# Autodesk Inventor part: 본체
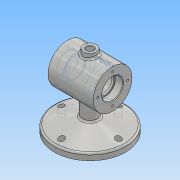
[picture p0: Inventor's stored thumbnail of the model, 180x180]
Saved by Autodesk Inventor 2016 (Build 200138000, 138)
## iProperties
Created: 2018-12
Part Number: 본체
Material: 알루미늄 6061
Document SubType Name: Modeling
Designer: Administrator
Density: 2.7 g/cm^3
Appearance: 알루미늄 - 평지
Mass: 664.863 g
Surface Area: 549.946 cm^2
Volume: 246.246 cm^3
Author: Administrator
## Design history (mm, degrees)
sketch "스케치2"
  geometry: L1 (0, 0)-(70, 0); L2 (70, 0)-(70, 30); L3 (70, 30)-(0, 30); L4 (0, 30)-(0, 0); L5 (0, 16)-(12, 16); L6 (12, 16)-(12, 14); L7 (12, 14)-(15, 14); L8 (15, 14)-(15, 25); L9 (15, 25)-(55, 25); L10 (55, 25)-(55, 14); L11 (55, 14)-(58, 14); L12 (58, 14)-(58, 16); L13 (58, 16)-(70, 16)
  constraints: 26 end point, 7 perpendicular, 6 point on line, 2 horizontal, 2 parallel
  dimensions: "d0" = 70 distance between parallel lines of L2 L4; "d1" = 32 diameter of L5 L1; "d2" = 28 diameter of L7 L1; "d3" = 3 distance between parallel lines of L6 L8; "d4" = 50 diameter of L9 L1; "d5" = 3 distance between parallel lines of L12 L10; "d6" = 60 diameter of L3 L1; "d13" = 40 distance between parallel lines of L10 L8; "d14" = 12 distance between parallel lines of L4 L6
revolve "회전1" sketch "스케치2" stored, may be unused: angle "d7" = 90 deg
fillet "모깎기1" dims "d8" = 3
fillet "모깎기2" dims "d9" = 0.3
chamfer "모따기1" distance "d10" = 1; stored, may be unused: second distance "d11" = 2, angle "d12" = 45 deg
node "작업 평면1"
sketch "스케치3"
  geometry: L1 (0, -30)-(0, 30) reference; L2 (0, 30)-(70, 30) reference; L3 (0, -30)-(70, -30) reference; L4 (35, 30)-(35, -30); C1 r 10 at (35, 0); 2 further points
  constraints: 3 midpoint, 2 end point, 1 centre point, 1 coincident
  dimensions: "d16" = 20 diameter of C1; "d19" = 35 distance between parallel lines of L1 L4 (derived)
extrude "돌출1" join sketch "스케치3" stored distance "d20" = 7; taper "d21" = 0 deg
hole "구멍1" diameter "d24" = 10; stored, may be unused: countersink angle "d28" = 90 deg, drill point angle "d30" = 0 deg; dims "d22" = 10, "d23" = 10, "d25" = 6, "d26" = 4, "d27" = 2, "d29" = 8
chamfer "모따기2" distance "d31" = 1; stored, may be unused: second distance "d32" = 2, angle "d33" = 45 deg
sketch "스케치4" dims "d34" = 46
  geometry: L1 (0, 0)-(-30, 0); 3 further points
  constraints: 2 end point, 2 horizontal alignment, 1 coincident, 1 horizontal, 1 point on line, 3 other
hole "구멍2" sketch "스케치4" at (-23, 0) diameter "d35" = 3.242; stored, may be unused: countersink angle "d39" = 90 deg, drill point angle "d41" = 118 deg; dims "d36" = 8, "d37" = 12.24, "d38" = 3.58, "d40" = 10
node "작업 평면2"
fillet "모깎기3" dims "d46" = 3
node "작업 평면3"
sketch "스케치5"
  geometry: L1 (52, 25)-(52, -25) reference; L2 (18, -25)-(18, 25) reference; C1 r 55 at (35, 0); 3 further points
  constraints: 1 centre point, 1 vertical alignment, 2 other
  dimensions: "d48" = 110 diameter of C1
extrude "돌출2" join sketch "스케치5" distance "d49" = 10; taper "d50" = 0 deg
sketch "스케치6" dims "d51" = 88
  geometry: L1 (0, 0)-(0, -44); C1 r 55 at (0, 0) reference; C2 r 44 at (0, 0); 1 further point
  constraints: 2 coincident, 2 end point, 1 centre point, 1 vertical, 1 vertical alignment, 3 other
extrude "돌출3" join sketch "스케치6" distance "d52" = 11; taper "d53" = -75 deg
sketch "스케치8"
  geometry: C1 r 13.947 at (0, 0) reference; C2 r 12 at (0, 0); 1 further point
  constraints: 1 centre point, 1 coincident
  dimensions: "d58" = 24 diameter of C2
extrude "돌출4" join sketch "스케치8" stored distance "d59" = 1; taper "d60" = 0 deg
fillet "모깎기4" dims "d61" = 3
fillet "모깎기5" dims "d62" = 3
sketch "스케치10" dims "d63" = 88
  geometry: L1 (0, 0)-(0, -44); C1 r 55 at (0, 0) reference; 2 further points
  constraints: 2 coincident, 2 end point, 1 vertical, 1 vertical alignment, 2 other
hole "구멍3" sketch "스케치10" at (0, -44) diameter "d64" = 9; stored, may be unused: countersink angle "d68" = 90 deg, drill point angle "d70" = 0 deg; dims "d65" = 8, "d66" = 14, "d67" = 14, "d69" = 10
node "작업 평면4"
sketch "스케치11"
  geometry: L1 (0, 30)-(-70, 30) reference; L2 (-70, 30)-(-70, -30) reference; 2 further points
  constraints: 1 other
  dimensions: "d75" = 35 distance from line of L2 point (-35, 0); "d76" = 30 distance from line of L1 point (-35, 0)
feature "엠보싱1" sketch "스케치11" dims "d0" = 70, "d1" = 32, "d2" = 28, "d3" = 3, "d4" = 50, "d5" = 3, "d6" = 60, "d13" = 40, "d14" = 12, "d77" = 0.5, "d78" = 0
node "솔리드1"
pattern_circular "원형 패턴1" dims angle "d43" = 360 deg
mirror "대칭1"
pattern_circular "원형 패턴2" dims angle "d72" = 360 deg
node "투영된 루프1"
node "절단 모서리 투영1"
node "절단 모서리 투영3"
other parameters: "d15" = 37, "d45" = 35, "d47" = -75, "d74" = 30.75
